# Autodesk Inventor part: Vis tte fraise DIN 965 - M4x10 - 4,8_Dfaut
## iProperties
Created: 2007-07
Part Number: Vis tte fraise DIN 965 - M4x10 - 4,8_Dfaut
Document SubType Name: Modeling
Designer: EF
Density: 1 g/cm^3
Author: EF
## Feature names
1. Base1
